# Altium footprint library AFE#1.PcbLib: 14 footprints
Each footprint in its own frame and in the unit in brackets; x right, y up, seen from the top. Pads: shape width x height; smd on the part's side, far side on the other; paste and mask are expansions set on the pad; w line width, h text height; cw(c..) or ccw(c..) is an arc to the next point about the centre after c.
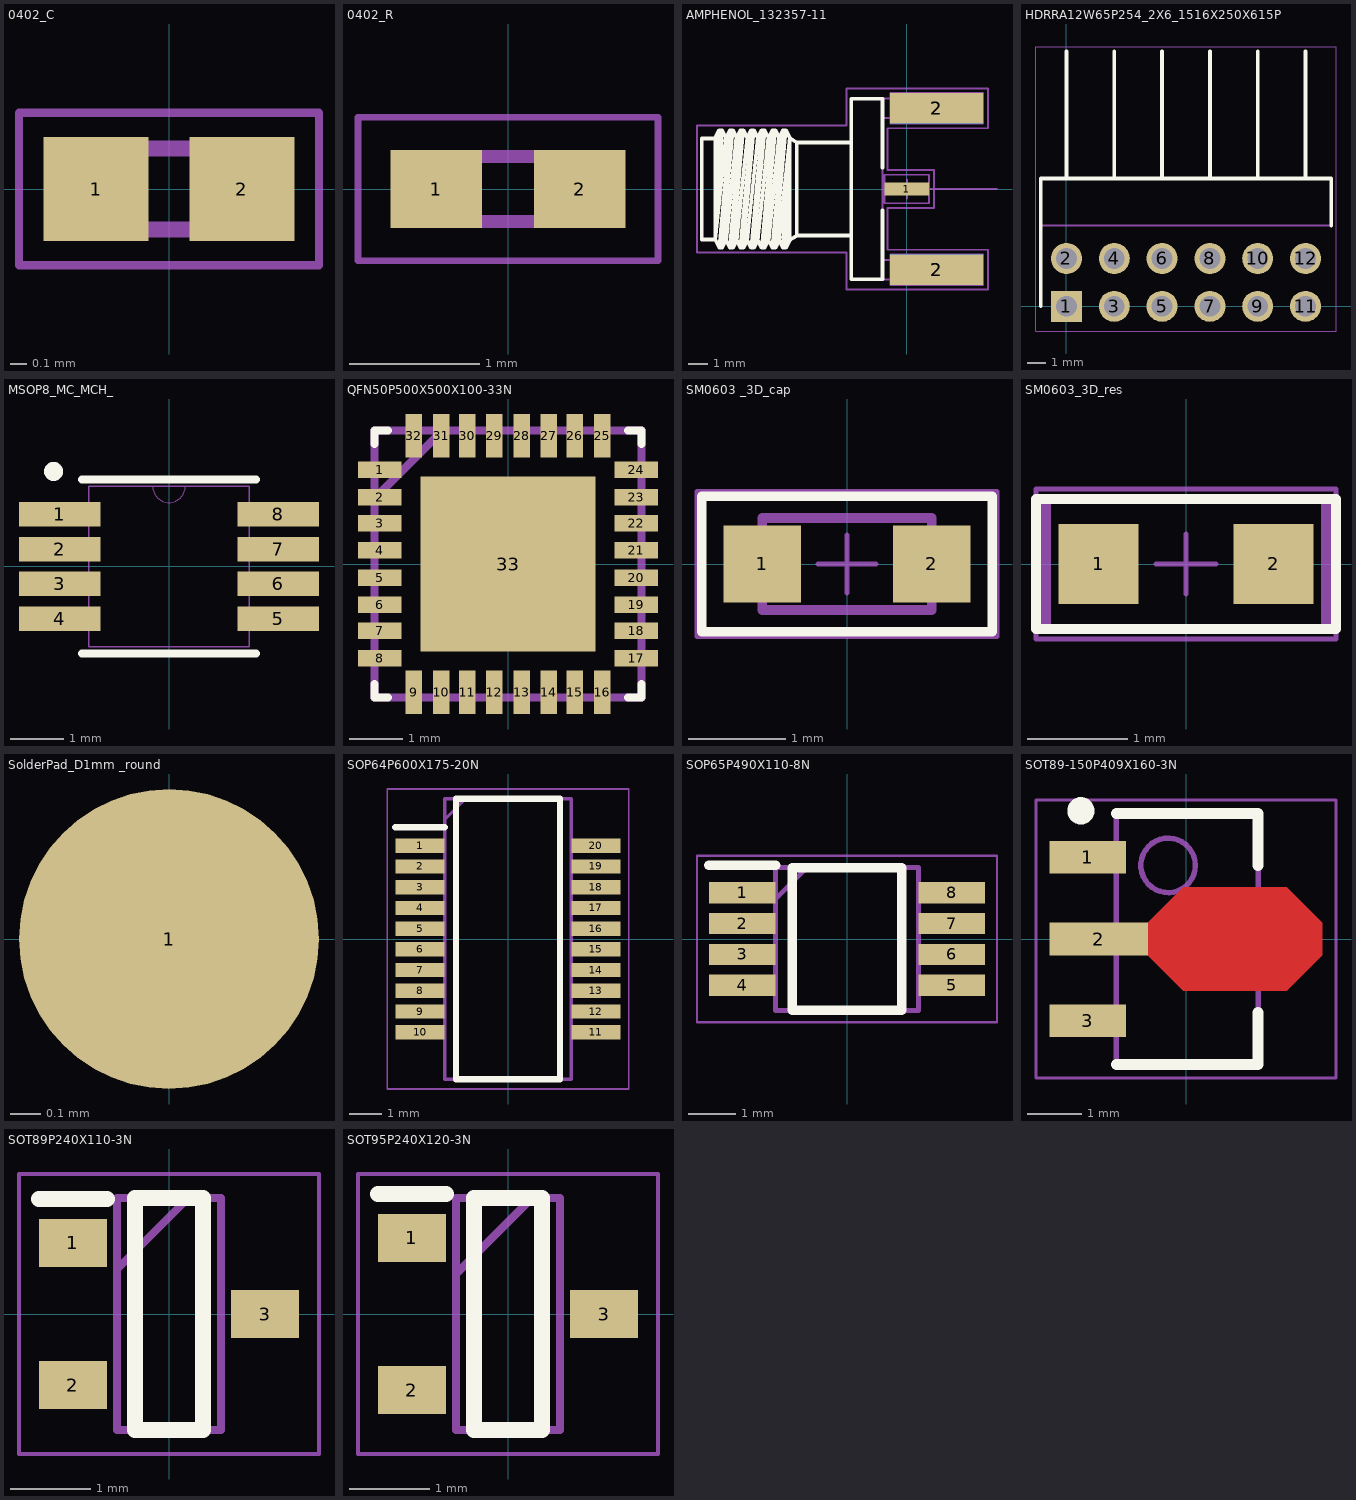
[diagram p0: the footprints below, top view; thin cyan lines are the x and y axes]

## 0402_C [mm]
pads (2):
  rect 0.65x0.64 smd: 1(-0.45,0) 2(0.45,0)
Mechanical 13:
  lines w0.1: -0.5,-0.25 -0.5,0.25 0.5,0.25 0.5,-0.25 -0.5,-0.25
Mechanical 15:
  lines w0.05: -0.925,-0.47 -0.925,0.47 0.925,0.47 0.925,-0.47 -0.925,-0.47
3D body "04023A100CAT2A.stp": height 0.56, standoff 0, extent -0.5,-0.25 0.5,0.25

## 0402_R [mm]
pads (2):
  rect 0.7x0.6 smd: 1(-0.55,0) 2(0.55,0)
Mechanical 13:
  lines w0.1: -0.5,-0.25 0.5,-0.25 0.5,0.25 -0.5,0.25 -0.5,-0.25
Mechanical 15:
  lines w0.05: -1.15,-0.55 1.15,-0.55 1.15,0.55 -1.15,0.55 -1.15,-0.55
3D body "CPF0402B100KE.stp": height 0.35, standoff 0, extent -0.5,-0.25 0.5,0.25

## AMPHENOL_132357-11 [mm]
pads (5):
  rect 2.35x0.7 smd: 1(0,0)
  rect 4.9x1.6 smd: 2(1.575,-4.25) 2(1.575,4.25)
  rect 4.9x1.6 smd far side: 2(1.575,-4.25) 2(1.575,4.25)
Top Overlay:
  lines w0.2: -10.09,2.665 -10.805,2.665 -10.805,-2.665 -10.09,-2.665 ; -6.17,-2.665 -5.795,-2.453 ; -2.925,-2.453 -5.795,-2.453 ; -2.925,2.447 -5.795,2.447 ; -1.275,-1.137 -1.275,-4.76 -2.925,-4.76 -2.925,4.76 -1.275,4.76 -1.275,1.137 ; -10.09,-2.665 -10.09,2.715 -9.879,3.094 ; -10.09,-2.665 -9.879,-3.094 ; -10.09,-2.665 -9.53,2.715 ; -10.09,-2.665 -9.741,3.094 ; -10.09,-2.665 -9.879,3.094 ; -9.879,-3.094 -9.741,-3.094 ; -9.879,-3.094 -9.319,3.094 ; -9.879,3.094 -9.741,3.094 ; -9.741,-3.094 -9.53,-2.715 ; -9.741,-3.094 -9.181,3.094 ; -9.741,3.094 -9.53,2.715 ; -9.53,-2.715 -9.319,-3.094 ; -9.53,-2.715 -8.97,2.715 ; -9.53,2.715 -9.319,3.094 ; -9.319,-3.094 -9.181,-3.094 ; -9.319,-3.094 -8.759,3.094 ; -9.319,3.094 -9.181,3.094 ; -9.181,-3.094 -8.97,-2.715 ; -9.181,-3.094 -8.621,3.094 ; -9.181,3.094 -8.97,2.715 ; -8.97,-2.715 -8.759,-3.094 ; -8.97,-2.715 -8.41,2.715 ; -8.97,2.715 -8.759,3.094 ; -8.759,-3.094 -8.621,-3.094 ; -8.759,-3.094 -8.199,3.094 ; -8.759,3.094 -8.621,3.094 ; -8.621,-3.094 -8.41,-2.715 ; -8.621,-3.094 -8.061,3.094 ; -8.621,3.094 -8.41,2.715 ; -8.41,-2.715 -8.199,-3.094 ; -8.41,-2.715 -7.85,2.715 ; -8.41,2.715 -8.199,3.094 ; -8.199,-3.094 -8.061,-3.094 ; -8.199,-3.094 -7.639,3.094 ; -8.199,3.094 -8.061,3.094 ; -8.061,-3.094 -7.85,-2.715 ; -8.061,-3.094 -7.501,3.094 ; -8.061,3.094 -7.85,2.715 ; -7.85,-2.715 -7.639,-3.094 ; -7.85,-2.715 -7.29,2.715 ; -7.85,2.715 -7.639,3.094 ; -7.639,-3.094 -7.501,-3.094 ; -7.639,-3.094 -7.079,3.094 ; -7.639,3.094 -7.501,3.094 ; -7.501,-3.094 -7.29,-2.715 ; -7.501,-3.094 -6.941,3.094 ; -7.501,3.094 -7.29,2.715 ; -7.29,-2.715 -7.079,-3.094 ; -7.29,-2.715 -6.73,2.715 ; -7.29,2.715 -7.079,3.094 ; -7.079,-3.094 -6.941,-3.094 ; -7.079,-3.094 -6.519,3.094 ; -7.079,3.094 -6.941,3.094 ; -6.941,-3.094 -6.73,-2.715 ; -6.941,-3.094 -6.381,3.094 ; -6.941,3.094 -6.73,2.715 ; -6.73,-2.715 -6.519,-3.094 ; -6.73,-2.715 -6.17,2.713 ; -6.73,2.715 -6.519,3.094 ; -6.519,-3.094 -6.381,-3.094 ; -6.519,-3.094 -6.17,2.713 ; -6.519,3.094 -6.381,3.094 ; -6.381,-3.094 -6.17,-2.715 -6.17,2.713 ; -6.381,-3.094 -6.17,2.665 -5.795,2.447 ; -6.381,3.094 -6.17,2.713 ; -5.795,-2.453 -5.795,2.447
Mechanical 8:
  lines w0.1: -0.5,0 0,0 ; 0,-0.5 0,0 ; 0,0.5 0,0 ; 0.5,0 0,0 ; 1.075,-4.25 1.575,-4.25 ; 1.075,4.25 1.575,4.25 ; 1.575,-4.75 1.575,-4.25 ; 1.575,-3.75 1.575,-4.25 ; 1.575,3.75 1.575,4.25 ; 1.575,4.75 1.575,4.25 ; 2.075,-4.25 1.575,-4.25 ; 2.075,4.25 1.575,4.25 ; -1.175,-0.75 -1.175,0.75 1.175,0.75 1.175,-0.75 -1.175,-0.75 ; -0.875,-5.05 4.025,-5.05 4.025,-3.45 -0.875,-3.45 -0.875,-5.05 ; -0.875,3.45 4.025,3.45 4.025,5.05 -0.875,5.05 -0.875,3.45
Mechanical 14:
  lines w0.1: -10.09,2.665 -10.805,2.665 -10.805,-2.665 -10.09,-2.665 ; -6.17,-2.665 -5.795,-2.453 ; -2.925,-2.453 -5.795,-2.453 ; -2.925,2.447 -5.795,2.447 ; -1.275,-4.76 -1.275,0 ; -1.275,-3.74 3.475,-3.74 3.475,-4.76 -2.925,-4.76 -2.925,4.76 3.475,4.76 3.475,3.74 -1.275,3.74 ; -1.275,-0.251 0.635,-0.251 0.635,0.251 -1.275,0.251 ; -1.275,4.76 -1.275,0 ; 4.75,0 -1.275,0 ; -10.09,-2.665 -10.09,2.715 -9.879,3.094 ; -10.09,-2.665 -9.879,-3.094 ; -10.09,-2.665 -9.53,2.715 ; -10.09,-2.665 -9.741,3.094 ; -10.09,-2.665 -9.879,3.094 ; -9.879,-3.094 -9.741,-3.094 ; -9.879,-3.094 -9.319,3.094 ; -9.879,3.094 -9.741,3.094 ; -9.741,-3.094 -9.53,-2.715 ; -9.741,-3.094 -9.181,3.094 ; -9.741,3.094 -9.53,2.715 ; -9.53,-2.715 -9.319,-3.094 ; -9.53,-2.715 -8.97,2.715 ; -9.53,2.715 -9.319,3.094 ; -9.319,-3.094 -9.181,-3.094 ; -9.319,-3.094 -8.759,3.094 ; -9.319,3.094 -9.181,3.094 ; -9.181,-3.094 -8.97,-2.715 ; -9.181,-3.094 -8.621,3.094 ; -9.181,3.094 -8.97,2.715 ; -8.97,-2.715 -8.759,-3.094 ; -8.97,-2.715 -8.41,2.715 ; -8.97,2.715 -8.759,3.094 ; -8.759,-3.094 -8.621,-3.094 ; -8.759,-3.094 -8.199,3.094 ; -8.759,3.094 -8.621,3.094 ; -8.621,-3.094 -8.41,-2.715 ; -8.621,-3.094 -8.061,3.094 ; -8.621,3.094 -8.41,2.715 ; -8.41,-2.715 -8.199,-3.094 ; -8.41,-2.715 -7.85,2.715 ; -8.41,2.715 -8.199,3.094 ; -8.199,-3.094 -8.061,-3.094 ; -8.199,-3.094 -7.639,3.094 ; -8.199,3.094 -8.061,3.094 ; -8.061,-3.094 -7.85,-2.715 ; -8.061,-3.094 -7.501,3.094 ; -8.061,3.094 -7.85,2.715 ; -7.85,-2.715 -7.639,-3.094 ; -7.85,-2.715 -7.29,2.715 ; -7.85,2.715 -7.639,3.094 ; -7.639,-3.094 -7.501,-3.094 ; -7.639,-3.094 -7.079,3.094 ; -7.639,3.094 -7.501,3.094 ; -7.501,-3.094 -7.29,-2.715 ; -7.501,-3.094 -6.941,3.094 ; -7.501,3.094 -7.29,2.715 ; -7.29,-2.715 -7.079,-3.094 ; -7.29,-2.715 -6.73,2.715 ; -7.29,2.715 -7.079,3.094 ; -7.079,-3.094 -6.941,-3.094 ; -7.079,-3.094 -6.519,3.094 ; -7.079,3.094 -6.941,3.094 ; -6.941,-3.094 -6.73,-2.715 ; -6.941,-3.094 -6.381,3.094 ; -6.941,3.094 -6.73,2.715 ; -6.73,-2.715 -6.519,-3.094 ; -6.73,-2.715 -6.17,2.713 ; -6.73,2.715 -6.519,3.094 ; -6.519,-3.094 -6.381,-3.094 ; -6.519,-3.094 -6.17,2.713 ; -6.519,3.094 -6.381,3.094 ; -6.381,-3.094 -6.17,-2.715 -6.17,2.713 ; -6.381,-3.094 -6.17,2.665 -5.795,2.447 ; -6.381,3.094 -6.17,2.713 ; -5.795,-2.453 -5.795,2.447
Mechanical 15:
  lines w0.1: -11.055,-3.344 -3.175,-3.344 -3.175,-5.3 4.275,-5.3 4.275,-3.2 -1.025,-3.2 -1.025,-1 1.425,-1 1.425,1 -1.025,1 -1.025,3.2 4.275,3.2 4.275,5.3 -3.175,5.3 -3.175,3.344 -11.055,3.344 -11.055,-3.344
3D body "AMPHENOL_132357-11.stp": height 4.08, standoff -3.84, extent -10.805,-4.76 3.475,4.76

## HDRRA12W65P254_2X6_1516X250X615P [mm]
pads (12):
  rect 1.65x1.65 hole 1.1: 1(0,0)
  round 1.65 hole 1.1: 2(0,2.54) 3(2.54,0) 4(2.54,2.54) 5(5.08,0) 6(5.08,2.54) 7(7.62,0) 8(7.62,2.54) 9(10.16,0) 10(10.16,2.54) 11(12.7,0) 12(12.7,2.54)
Top Overlay:
  lines w0.2: -1.37,0 -1.37,6.79 14.07,6.79 14.07,4.29 ; 0,6.79 0,13.54 ; 2.54,6.79 2.54,13.54 ; 5.08,6.79 5.08,13.54 ; 7.62,6.79 7.62,13.54 ; 10.16,6.79 10.16,13.54 ; 12.7,6.79 12.7,13.54
Mechanical 13:
  lines w0.1: -1.37,4.29 14.07,4.29 14.07,6.79 -1.37,6.79 -1.37,4.29
Mechanical 15:
  lines w0.05: -1.62,-1.325 -1.62,13.79 14.32,13.79 14.32,-1.325 -1.62,-1.325
3D body "90122-0126.stp": height 6.16, standoff -2.89, extent -1.27,-0.4 13.97,13.465

## MSOP8_MC_MCH_ [mil]
pads (8):
  rect 60x18 smd paste+0 mask+0: 1(-80.5,38.39) 2(-80.5,12.8) 3(-80.5,-12.8) 4(-80.5,-38.39) 5(80.5,-38.39) 6(80.5,-12.8) 7(80.5,12.8) 8(80.5,38.39)
Top Overlay:
  circle w10: c-85,70 r2
  lines w6: -64,-64 64,-64 ; -64,64 64,64
Mechanical 13:
  lines w0: -12,59 ccw(c0,59) 12,59
  lines w1: -96.5,-46.39 -59,-46.39 -59,-30.39 -96.5,-30.39 -96.5,-46.39 ; -96.5,-20.8 -59,-20.8 -59,-4.8 -96.5,-4.8 -96.5,-20.8 ; -96.5,4.8 -59,4.8 -59,20.8 -96.5,20.8 -96.5,4.8 ; -96.5,30.39 -59,30.39 -59,46.39 -96.5,46.39 -96.5,30.39 ; -59,-59 -59,59 59,59 59,-59 -59,-59 ; 59,-46.39 96.5,-46.39 96.5,-30.39 59,-30.39 59,-46.39 ; 59,-20.8 96.5,-20.8 96.5,-4.8 59,-4.8 59,-20.8 ; 59,4.8 96.5,4.8 96.5,20.8 59,20.8 59,4.8 ; 59,30.39 96.5,30.39 96.5,46.39 59,46.39 59,30.39
3D body "MSOP8_MC_MCH.step": height 43.11, standoff 0, extent -96.5,-59.02 96.5,59.02

## QFN50P500X500X100-33N [mil]
pads (33):
  rect 32x12 smd: 1(-94,69) 2(-94,49) 3(-94,30) 4(-94,10) 5(-94,-10) 6(-94,-30) 7(-94,-49) 8(-94,-69) 17(94,-69) 18(94,-49) 19(94,-30) 20(94,-10) 21(94,10) 22(94,30) 23(94,49) 24(94,69)
  rect 12x32 smd: 9(-69,-94) 10(-49,-94) 11(-30,-94) 12(-10,-94) 13(10,-94) 14(30,-94) 15(49,-94) 16(69,-94) 25(69,94) 26(49,94) 27(30,94) 28(10,94) 29(-10,94) 30(-30,94) 31(-49,94) 32(-69,94)
  rect 128x128 smd: 33(0,0)
Top Overlay:
  lines w6: -98,-88 -98,-98 -88,-98 ; -98,88 -98,98 -88,98 ; 88,-98 98,-98 98,-88 ; 88,98 98,98 98,88
Mechanical 13:
  lines w6: -98,-75 -98,-63 ; -98,-55 -98,-43 ; -98,-36 -98,-24 ; -98,-16 -98,-4 ; -98,4 -98,16 ; -98,24 -98,36 ; -98,43 -98,55 ; -98,48 -48,98 ; -98,63 -98,75 ; -75,-98 -63,-98 ; -75,98 -63,98 ; -55,-98 -43,-98 ; -55,98 -43,98 ; -36,-98 -24,-98 ; -36,98 -24,98 ; -16,-98 -4,-98 ; -16,98 -4,98 ; 4,-98 16,-98 ; 4,98 16,98 ; 24,-98 36,-98 ; 24,98 36,98 ; 43,-98 55,-98 ; 43,98 55,98 ; 63,-98 75,-98 ; 63,98 75,98 ; 98,-75 98,-63 ; 98,-55 98,-43 ; 98,-36 98,-24 ; 98,-16 98,-4 ; 98,4 98,16 ; 98,24 98,36 ; 98,43 98,55 ; 98,63 98,75 ; -98,-98 -98,98 98,98 98,-98 -98,-98

## SM0603 _3D_cap [mm]
pads (2):
  rect 0.8x0.8 smd: 1(-0.875,0) 2(0.875,0)
Top Overlay:
  lines w0.1: -1.5,-0.7 -1.5,0.7 1.5,0.7 1.5,-0.7 -1.5,-0.7
Mechanical 14:
  lines w0.1: -0.875,-0.475 -0.875,0.475 0.875,0.475 0.875,-0.475 -0.875,-0.475
Mechanical 15:
  lines w0.05: -0.3,0 0.3,0 ; 0,-0.3 0,0.3 ; -1.55,-0.75 1.55,-0.75 1.55,0.75 -1.55,0.75 -1.55,-0.75
3D body "CAPC1608X87N.stp": height 0.87, standoff 0, extent -0.875,-0.475 0.875,0.475

## SM0603_3D_res [mm]
pads (2):
  rect 0.8x0.8 smd: 1(-0.875,0) 2(0.875,0)
Top Overlay:
  lines w0.1: -1.5,-0.65 -1.5,0.65 1.5,0.65 1.5,-0.65 -1.5,-0.65
Mechanical 14:
  lines w0.1: -1.4,-0.65 -1.4,0.65 1.4,0.65 1.4,-0.65 -1.4,-0.65
Mechanical 15:
  lines w0.05: -0.3,0 0.3,0 ; 0,-0.3 0,0.3 ; -1.5,-0.75 1.5,-0.75 1.5,0.75 -1.5,0.75 -1.5,-0.75
3D body "RESC1608X55N.stp": height 0.55, standoff 0, extent -0.875,-0.475 0.875,0.475

## SolderPad_D1mm _round [mm]
pads (1):
  round 1 smd: 1(0,0)

## SOP64P600X175-20N [mm]
pads (20):
  rect 1.52x0.44 smd: 1(-2.715,2.88) 2(-2.715,2.24) 3(-2.715,1.6) 4(-2.715,0.96) 5(-2.715,0.32) 6(-2.715,-0.32) 7(-2.715,-0.96) 8(-2.715,-1.6) 9(-2.715,-2.24) 10(-2.715,-2.88) 11(2.715,-2.88) 12(2.715,-2.24) 13(2.715,-1.6) 14(2.715,-0.96) 15(2.715,-0.32) 16(2.715,0.32) 17(2.715,0.96) 18(2.715,1.6) 19(2.715,2.24) 20(2.715,2.88)
Top Overlay:
  lines w0.2: -3.475,3.45 -1.955,3.45 ; -1.605,-4.328 -1.605,4.328 1.605,4.328 1.605,-4.328 -1.605,-4.328
Mechanical 13:
  lines w0.1: -1.955,3.688 -1.315,4.328 ; -1.955,-4.328 -1.955,4.328 1.955,4.328 1.955,-4.328 -1.955,-4.328
Mechanical 15:
  lines w0.05: -3.725,-4.63 -3.725,4.63 3.725,4.63 3.725,-4.63 -3.725,-4.63
3D body "AD8331ARQZ.stp": height 1.75, standoff 0, extent -2.997,-4.327 2.997,4.327

## SOP65P490X110-8N [mm]
pads (8):
  rect 1.4x0.45 smd: 1(-2.2,0.975) 2(-2.2,0.325) 3(-2.2,-0.325) 4(-2.2,-0.975) 5(2.2,-0.975) 6(2.2,-0.325) 7(2.2,0.325) 8(2.2,0.975)
Top Overlay:
  lines w0.2: -2.9,1.55 -1.5,1.55 ; -1.15,-1.5 1.15,-1.5 1.15,1.5 -1.15,1.5 -1.15,-1.5
Mechanical 13:
  lines w0.1: -1.5,0.85 -0.85,1.5 ; -1.5,-1.5 1.5,-1.5 1.5,1.5 -1.5,1.5 -1.5,-1.5
Mechanical 15:
  lines w0.05: -3.15,-1.75 3.15,-1.75 3.15,1.75 -3.15,1.75 -3.15,-1.75
3D body "MCP4812-E_MS.stp": height 1.1, standoff 0, extent -2.45,-1.5 2.45,1.5

## SOT89-150P409X160-3N [mm]
pads (3):
  rect 1.4x0.6 smd: 1(-1.8,1.5) 3(-1.8,-1.5)
  rect 1.8x0.6 smd: 2(-1.6,0)
Top Layer:
  region: -0.7,0.3 -0.05,0.95 1.85,0.95 2.5,0.3 2.5,-0.3 1.85,-0.95 -0.05,-0.95 -0.7,-0.3
Top Overlay:
  circle w0.25: c-1.927,2.35 r0.125
  lines w0.2: -1.278,-2.3 1.322,-2.3 1.322,-1.35 ; -1.278,2.3 1.322,2.3 1.322,1.35
Mechanical 13:
  circle w0.1: c-0.327,1.35 r0.5
  lines w0.1: -1.278,-2.3 1.322,-2.3 1.322,2.3 -1.278,2.3 -1.278,-2.3
Mechanical 15:
  lines w0.05: -2.75,-2.55 2.75,-2.55 2.75,2.55 -2.75,2.55 -2.75,-2.55
  lines w0.1: -0.477,0 0.523,0 ; 0.022,-0.5 0.022,0.5
3D body: height 1.6, standoff 0, extent -1.278,-2.3 1.322,2.3

## SOT89P240X110-3N [mm]
pads (3):
  rect 0.85x0.6 smd: 1(-1.2,0.89) 2(-1.2,-0.89) 3(1.2,0)
Top Overlay:
  lines w0.2: -1.625,1.44 -0.775,1.44 ; -0.425,-1.45 0.425,-1.45 0.425,1.45 -0.425,1.45 -0.425,-1.45
Mechanical 13:
  lines w0.1: -0.65,0.56 0.24,1.45 ; -0.65,-1.45 0.65,-1.45 0.65,1.45 -0.65,1.45 -0.65,-1.45
Mechanical 15:
  lines w0.05: -1.875,-1.75 1.875,-1.75 1.875,1.75 -1.875,1.75 -1.875,-1.75
3D body "AP2127N-3.3TRG1.stp": height 1.1, standoff 0, extent -1.2,-1.45 1.2,1.45

## SOT95P240X120-3N [mm]
pads (3):
  rect 0.85x0.6 smd: 1(-1.2,0.95) 2(-1.2,-0.95) 3(1.2,0)
Top Overlay:
  lines w0.2: -1.625,1.5 -0.775,1.5 ; -0.425,-1.45 -0.425,1.45 0.425,1.45 0.425,-1.45 -0.425,-1.45
Mechanical 13:
  lines w0.1: -0.65,0.5 0.3,1.45 ; -0.65,-1.45 -0.65,1.45 0.65,1.45 0.65,-1.45 -0.65,-1.45
Mechanical 15:
  lines w0.05: -1.875,-1.75 -1.875,1.75 1.875,1.75 1.875,-1.75 -1.875,-1.75
3D body "BAV99-7-F.stp": height 1.2, standoff 0, extent -1.2,-1.45 1.2,1.45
